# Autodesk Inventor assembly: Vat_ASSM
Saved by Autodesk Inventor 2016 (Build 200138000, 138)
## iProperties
Created: 2015-11
Part Number: Vat_ASSM
Document SubType Name: Assembly
Designer: John
Author: John
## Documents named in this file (4)
- D:\3D Printer Designs\John Ledden Designs\DLP Printer\V0-4\Vat_ASSM.iam
- D:\3D Printer Designs\John Ledden Designs\DLP Printer\V0-4\Vat_MountingPlate.ipt
- D:\3D Printer Designs\John Ledden Designs\DLP Printer\V0-4\M8_Rod_275mm.ipt
- D:\3D Printer Designs\John Ledden Designs\DLP Printer\V0-4\FlexVat_ASSM.iam
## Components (4 placed, 4 different names)
1. Vat_MountingPlate_1083
2. M8_Rod_275mm_1084
3. M8_Rod_275mm_1085
4. FlexVat_ASSM_1086 [sub-assembly]
